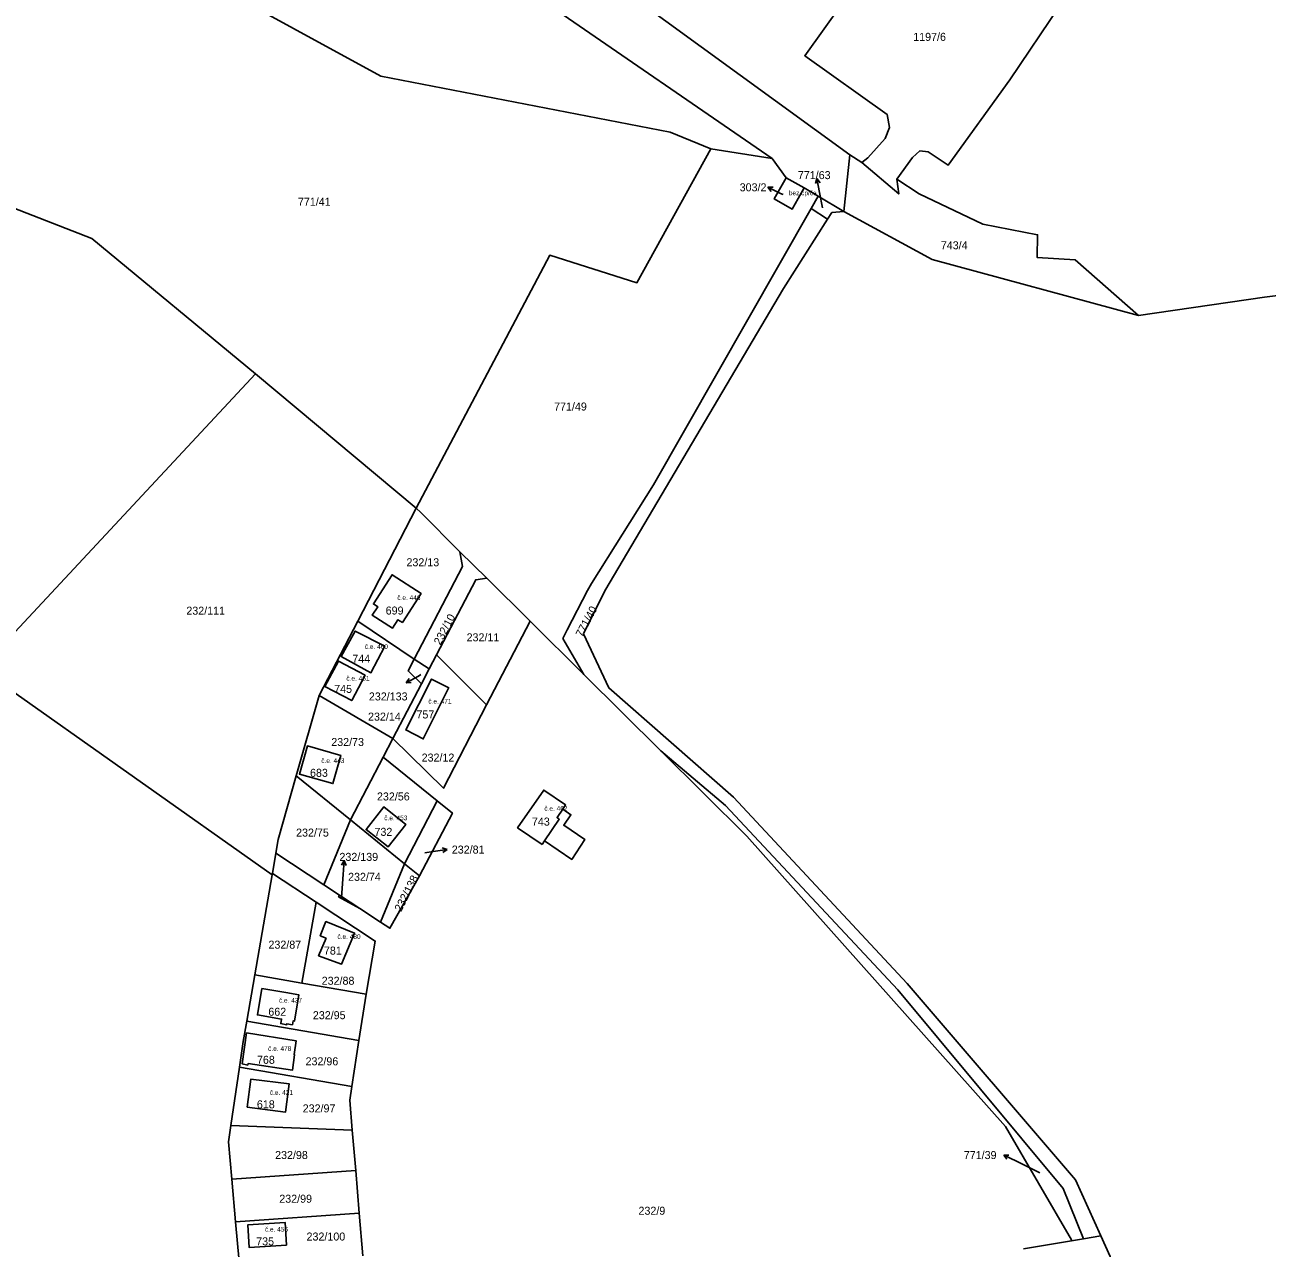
# Model space of a CAD drawing. Extents: x -887272 to -880188, y -1026687 to -1021896.
# Drawn here: x -882048.6 to -881784.7, y -1023602.5 to -1023342.6 of the extents above; entities that cross this region are included whole.
import ezdxf

# ---------------------------------------------------------------- set-up
doc = ezdxf.new("R2010")
doc.units = 0
for name, color, linetype in [('Definiční body', 7, 'Continuous'), ('Hranice parcel', 7, 'Continuous'), ('Parcelní čísla', 7, 'Continuous'), ('Polygon budovy', 7, 'Continuous'), ('Pop  PČ popisy', 7, 'Continuous'), ('Vnitřní kresba', 7, 'Continuous')]:
    doc.layers.add(name, color=color, linetype=linetype)

msp = doc.modelspace()

# ---------------------------------------------------------------- linework, layer by layer
at = {"layer": 'Hranice parcel'}
for p, q in [((-881902.88, -1023368.96), (-881889.86, -1023371.02)), ((-881873.32, -1023370.23), (-881874.58, -1023382.3)), ((-881873.32, -1023370.23), (-881870.82, -1023371.88)), ((-881886.87, -1023375.11), (-881889.86, -1023371.02)), ((-881883.05, -1023377.27), (-881886.87, -1023375.11)), ((-881880.08, -1023379.03), (-881883.05, -1023377.27)), ((-881881.58, -1023381.65), (-881880.08, -1023379.03)), ((-881880.08, -1023379.03), (-881874.58, -1023382.3)), ((-881878.1, -1023383.87), (-881881.58, -1023381.65)), ((-881999.63, -1023416.75), (-882058.02, -1023479.44)), ((-881965.46, -1023445.29), (-881999.63, -1023416.75)), ((-881965.46, -1023445.29), (-881977.86, -1023469.33)), ((-881964.49, -1023446.26), (-881965.46, -1023445.29)), ((-881956.17, -1023454.58), (-881964.49, -1023446.26)), ((-881950.44, -1023460.16), (-881956.17, -1023454.58)), ((-881941.26, -1023469.34), (-881950.44, -1023460.16)), ((-881977.86, -1023469.33), (-881986.1, -1023485.08)), ((-881977.86, -1023469.33), (-881965.87, -1023477.36)), ((-881941.26, -1023469.34), (-881950.54, -1023487.1)), ((-881929.87, -1023480.62), (-881941.26, -1023469.34)), ((-881934.3, -1023472.97), (-881929.87, -1023480.62)), ((-881965.87, -1023477.36), (-881962.71, -1023479.48)), ((-881962.71, -1023479.48), (-881961.18, -1023476.49)), ((-881961.18, -1023476.49), (-881950.54, -1023487.1)), ((-881996.08, -1023523.25), (-882058.02, -1023479.44)), ((-881962.71, -1023479.48), (-881964.33, -1023482.66)), ((-881913.49, -1023496.9), (-881929.87, -1023480.62)), ((-881964.33, -1023482.66), (-881970.4, -1023494.24)), ((-881986.1, -1023485.08), (-881990.93, -1023502.21)), ((-881986.1, -1023485.08), (-881970.4, -1023494.24)), ((-881970.4, -1023494.24), (-881972.46, -1023498.24)), ((-881895.21, -1023515.01), (-881913.49, -1023496.9)), ((-881972.46, -1023498.24), (-881979.39, -1023511.53)), ((-881972.46, -1023498.24), (-881961.04, -1023507.47)), ((-881990.93, -1023502.21), (-881979.39, -1023511.53)), ((-881967.93, -1023520.85), (-881961.04, -1023507.47)), ((-881979.39, -1023511.53), (-881985.07, -1023525.34)), ((-881979.39, -1023511.53), (-881967.93, -1023520.85)), ((-881995.28, -1023518.63), (-881996.02, -1023522.93)), ((-881985.07, -1023525.34), (-881995.28, -1023518.63)), ((-881973.03, -1023533.25), (-881967.93, -1023520.85)), ((-881967.93, -1023520.85), (-881964.73, -1023523.44)), ((-881999.76, -1023544.49), (-881996.08, -1023523.25)), ((-881996.02, -1023522.93), (-881996.08, -1023523.25)), ((-881996.02, -1023522.93), (-881986.75, -1023529.02)), ((-881981.77, -1023527.51), (-881985.07, -1023525.34)), ((-881989.73, -1023546.22), (-881986.75, -1023529.02)), ((-881981.77, -1023527.51), (-881977.45, -1023530.34)), ((-881973.03, -1023533.25), (-881977.45, -1023530.34)), ((-882001.46, -1023554.3), (-881999.76, -1023544.49)), ((-881999.76, -1023544.49), (-881989.73, -1023546.22)), ((-881989.73, -1023546.22), (-881976.11, -1023548.58)), ((-881976.11, -1023548.58), (-881977.63, -1023558.42)), ((-882001.46, -1023554.3), (-881977.63, -1023558.42)), ((-881977.63, -1023558.42), (-881979.14, -1023568.21)), ((-882004.86, -1023576.46), (-882003.02, -1023564.08)), ((-882003.02, -1023564.08), (-881979.14, -1023568.21)), ((-882004.86, -1023576.46), (-881979.04, -1023577.48)), ((-881979.04, -1023577.48), (-881978.32, -1023586.01)), ((-882004.66, -1023587.88), (-881978.32, -1023586.01)), ((-881978.32, -1023586.01), (-881977.56, -1023595.07)), ((-882003.86, -1023596.94), (-882004.66, -1023587.88)), ((-881825.37, -1023588.04), (-881820, -1023599.95)), ((-882003.86, -1023596.94), (-881977.56, -1023595.07)), ((-881977.56, -1023595.07), (-881976.82, -1023604.15)), ((-882003.11, -1023605.34), (-882003.86, -1023596.94)), ((-881820, -1023599.95), (-881823.68, -1023600.55)), ((-881836.44, -1023602.65), (-881826.23, -1023600.97)), ((-881826.23, -1023600.97), (-881826.27, -1023600.76)), ((-881823.68, -1023600.55), (-881826.23, -1023600.97))]:
    msp.add_line(p, q, dxfattribs=at)
for points in [[(-881889.86, -1023371.02), (-881937.66, -1023338.14), (-881972.84, -1023309.16), (-881998.01, -1023280.08)], [(-881964.8, -1023301.5), (-881943.98, -1023318.82), (-881873.32, -1023370.23)], [(-881870.82, -1023371.88), (-881869.52, -1023370.84), (-881865.81, -1023366.79), (-881864.94, -1023364.39), (-881865.44, -1023361.64), (-881882.9, -1023349.18), (-881858.96, -1023315.71), (-881828.68, -1023338.43), (-881839.34, -1023354.28), (-881852.45, -1023372.44), (-881856.71, -1023369.6), (-881858.46, -1023369.39), (-881860, -1023370.8), (-881863.33, -1023375.42)], [(-882044.17, -1023338.98), (-882010.08, -1023333.22), (-881972.96, -1023353.48), (-881911.54, -1023365.44), (-881902.88, -1023368.96)], [(-881965.46, -1023445.29), (-881937.09, -1023391.55), (-881918.59, -1023397.41), (-881902.88, -1023368.96)], [(-882081.8, -1023371.16), (-882063.68, -1023376.58), (-882034.36, -1023388.04), (-881999.63, -1023416.75)], [(-881863.33, -1023375.42), (-881862.95, -1023378.53), (-881870.82, -1023371.88)], [(-881886.87, -1023375.11), (-881889.4, -1023379.59), (-881885.57, -1023381.74), (-881883.05, -1023377.27)], [(-881863.33, -1023375.42), (-881858.6, -1023378.54), (-881845.06, -1023384.94), (-881833.44, -1023387.22), (-881833.52, -1023392.08), (-881825.44, -1023392.52), (-881812.02, -1023404.38)], [(-881878.1, -1023383.87), (-881887.44, -1023398.64), (-881925.36, -1023462.88), (-881929.94, -1023472.01), (-881924.53, -1023483.51), (-881898.05, -1023506.74), (-881861.18, -1023546.34), (-881825.37, -1023588.04)], [(-881881.58, -1023381.65), (-881915.08, -1023440.34), (-881928.2, -1023461.3), (-881929.08, -1023462.8)], [(-881874.58, -1023382.3), (-881877.13, -1023382.48), (-881878.1, -1023383.87)], [(-881874.58, -1023382.3), (-881855.84, -1023392.48), (-881812.02, -1023404.38)], [(-881754.99, -1023396.75), (-881785.26, -1023400.48), (-881812.02, -1023404.38)], [(-881956.17, -1023454.58), (-881955.61, -1023457.68), (-881965.87, -1023477.36)], [(-881968.4, -1023469.6), (-881969.34, -1023469.02), (-881970.53, -1023470.82), (-881974.81, -1023468.07), (-881973.64, -1023466.24), (-881974.57, -1023465.64), (-881970.59, -1023459.46), (-881964.43, -1023463.47), (-881968.4, -1023469.6)], [(-881961.18, -1023476.49), (-881952.8, -1023460.5), (-881950.44, -1023460.16)], [(-881929.08, -1023462.8), (-881933.38, -1023471.19), (-881934.3, -1023472.97)], [(-881975.1, -1023480.27), (-881981.44, -1023476.85), (-881978.46, -1023471.42), (-881972.16, -1023474.66), (-881975.1, -1023480.27)], [(-881984.84, -1023483.2), (-881981.95, -1023477.81), (-881976.31, -1023480.81), (-881979.17, -1023486.19), (-881984.84, -1023483.2)], [(-881964.33, -1023482.66), (-881967.19, -1023479.88), (-881965.87, -1023477.36)], [(-881958.55, -1023483.48), (-881958.59, -1023483.58), (-881961.69, -1023489.79), (-881963.96, -1023494.35), (-881967.69, -1023492.44), (-881962.21, -1023481.64), (-881958.55, -1023483.48)], [(-881950.54, -1023487.1), (-881959.68, -1023504.83), (-881970.4, -1023494.24)], [(-881990.29, -1023501.81), (-881988.59, -1023495.84), (-881981.47, -1023497.86), (-881983.17, -1023503.84), (-881990.29, -1023501.81)], [(-881823.68, -1023600.55), (-881828.03, -1023589.87), (-881863.15, -1023547.67), (-881899.78, -1023508.48), (-881913.49, -1023496.9)], [(-881990.93, -1023502.21), (-881994.77, -1023515.72), (-881995.28, -1023518.63)], [(-881938.71, -1023516.74), (-881943.92, -1023513.21), (-881938.38, -1023505.21), (-881933.74, -1023508.37), (-881934.34, -1023509.27), (-881932.58, -1023510.45), (-881934.1, -1023512.69), (-881929.62, -1023515.71), (-881932.43, -1023519.94), (-881938.21, -1023516.01), (-881938.71, -1023516.74)], [(-881961.04, -1023507.47), (-881957.76, -1023510.11), (-881964.73, -1023523.44)], [(-881967.69, -1023512.49), (-881971.43, -1023517.29), (-881976.11, -1023513.59), (-881972.37, -1023508.8), (-881967.69, -1023512.49)], [(-881826.27, -1023600.76), (-881840.27, -1023576.67), (-881895.21, -1023515.01)], [(-881964.73, -1023523.44), (-881971.06, -1023534.55), (-881973.03, -1023533.25)], [(-881986.75, -1023529.02), (-881974.15, -1023537.3), (-881976.11, -1023548.58)], [(-881977.45, -1023530.34), (-881981.97, -1023527.88), (-881981.77, -1023527.51)], [(-881984.59, -1023536.68), (-881985.85, -1023536.17), (-881984.63, -1023533.14), (-881978.56, -1023535.61), (-881981.36, -1023542.21), (-881986.2, -1023540.42), (-881984.59, -1023536.68)], [(-881994.23, -1023554.83), (-881994.06, -1023553.85), (-881999.19, -1023552.97), (-881998.23, -1023547.38), (-881993.16, -1023548.24), (-881990.39, -1023548.72), (-881991.35, -1023554.31), (-881991.62, -1023554.27), (-881991.76, -1023555.08), (-881992.96, -1023554.88), (-881992.99, -1023555.07), (-881994.23, -1023554.83)], [(-882003.02, -1023564.08), (-882002.21, -1023558.65), (-882001.46, -1023554.3)], [(-882001.49, -1023556.8), (-881991, -1023558.46), (-881991.41, -1023561.42), (-881991.3, -1023561.45), (-881991.74, -1023564.69), (-882001.18, -1023563.32), (-882001.24, -1023563.63), (-882002.41, -1023563.41), (-882001.49, -1023556.8)], [(-882001.35, -1023572.58), (-882000.59, -1023566.61), (-881992.44, -1023567.65), (-881993.21, -1023573.63), (-882001.35, -1023572.58)], [(-881979.14, -1023568.21), (-881979.58, -1023571.07), (-881979.04, -1023577.48)], [(-882004.66, -1023587.88), (-882005.37, -1023579.92), (-882004.86, -1023576.46)], [(-881993.01, -1023601.91), (-882000.94, -1023602.43), (-882001.25, -1023597.61), (-881993.3, -1023597.12), (-881993.01, -1023601.91)], [(-881818.23, -1023617.44), (-881818.12, -1023609.45), (-881818.05, -1023604.28), (-881820, -1023599.95)]]:
    msp.add_lwpolyline(points, dxfattribs=at)
at = {"layer": 'Polygon budovy'}
for points in [[(-881886.87, -1023375.11), (-881889.4, -1023379.59), (-881885.57, -1023381.74), (-881883.05, -1023377.27)], [(-881970.59, -1023459.46), (-881974.57, -1023465.64), (-881973.64, -1023466.24), (-881974.81, -1023468.07), (-881970.53, -1023470.82), (-881969.34, -1023469.02), (-881968.4, -1023469.6), (-881964.43, -1023463.47)], [(-881981.44, -1023476.85), (-881975.1, -1023480.27), (-881972.16, -1023474.66), (-881978.46, -1023471.42)], [(-881984.84, -1023483.2), (-881979.17, -1023486.19), (-881976.31, -1023480.81), (-881981.95, -1023477.81)], [(-881962.21, -1023481.64), (-881967.69, -1023492.44), (-881963.96, -1023494.35), (-881961.69, -1023489.79), (-881958.59, -1023483.58), (-881958.55, -1023483.48)], [(-881988.59, -1023495.84), (-881990.29, -1023501.81), (-881983.17, -1023503.84), (-881981.47, -1023497.86)], [(-881938.71, -1023516.74), (-881938.21, -1023516.01), (-881935.06, -1023511.39), (-881935.55, -1023511.06), (-881934.34, -1023509.27), (-881933.74, -1023508.37), (-881938.38, -1023505.21), (-881943.92, -1023513.21)], [(-881976.11, -1023513.59), (-881971.43, -1023517.29), (-881967.69, -1023512.49), (-881972.37, -1023508.8)], [(-881984.59, -1023536.68), (-881986.2, -1023540.42), (-881981.36, -1023542.21), (-881978.56, -1023535.61), (-881984.63, -1023533.14), (-881985.85, -1023536.17)], [(-881998.23, -1023547.38), (-881999.19, -1023552.97), (-881994.06, -1023553.85), (-881994.23, -1023554.83), (-881992.99, -1023555.07), (-881992.96, -1023554.88), (-881991.76, -1023555.08), (-881991.62, -1023554.27), (-881991.35, -1023554.31), (-881990.39, -1023548.72), (-881993.16, -1023548.24)], [(-882002.41, -1023563.41), (-882001.24, -1023563.63), (-882001.18, -1023563.32), (-881991.74, -1023564.69), (-881991.3, -1023561.45), (-881991.41, -1023561.42), (-881991, -1023558.46), (-882001.49, -1023556.8)], [(-882000.59, -1023566.61), (-882001.35, -1023572.58), (-881993.21, -1023573.63), (-881992.44, -1023567.65)], [(-881993.01, -1023601.91), (-881993.3, -1023597.12), (-882001.25, -1023597.61), (-882000.94, -1023602.43)]]:
    msp.add_lwpolyline(points, close=True, dxfattribs=at)
at = {"layer": 'Pop  PČ popisy'}
for p, q in [((-881880.34, -1023375.27), (-881880.64, -1023376.35)), ((-881879.77, -1023378.22), (-881880.34, -1023375.27)), ((-881880.34, -1023375.27), (-881879.66, -1023376.16)), ((-881890.74, -1023377.11), (-881889.62, -1023377.1)), ((-881888.04, -1023378.43), (-881890.74, -1023377.11)), ((-881890.74, -1023377.11), (-881890.06, -1023378)), ((-881887.5, -1023378.69), (-881888.04, -1023378.43)), ((-881879.14, -1023381.48), (-881879.77, -1023378.22)), ((-881964.99, -1023480.97), (-881967.61, -1023482.43)), ((-881967.61, -1023482.43), (-881966.98, -1023481.5)), ((-881964.49, -1023480.67), (-881964.99, -1023480.97)), ((-881967.61, -1023482.43), (-881966.5, -1023482.38)), ((-881963.61, -1023518.53), (-881961.87, -1023518.28)), ((-881961.87, -1023518.28), (-881958.9, -1023517.86)), ((-881958.9, -1023517.86), (-881959.96, -1023517.51)), ((-881958.9, -1023517.86), (-881959.82, -1023518.5)), ((-881980.77, -1023520.18), (-881981.34, -1023521.14)), ((-881980.98, -1023523.17), (-881980.77, -1023520.18)), ((-881980.77, -1023520.18), (-881980.34, -1023521.21)), ((-881981.32, -1023528.03), (-881980.98, -1023523.17)), ((-881840.65, -1023582.76), (-881839.53, -1023582.75)), ((-881837.95, -1023584.08), (-881840.65, -1023582.76)), ((-881840.65, -1023582.76), (-881839.97, -1023583.65)), ((-881832.97, -1023586.53), (-881837.95, -1023584.08))]:
    msp.add_line(p, q, dxfattribs=at)
at = {"layer": 'Vnitřní kresba'}
for p, q in [((-881935.55, -1023511.06), (-881934.34, -1023509.27)), ((-881938.21, -1023516.01), (-881935.06, -1023511.39)), ((-881935.06, -1023511.39), (-881935.55, -1023511.06))]:
    msp.add_line(p, q, dxfattribs=at)

# ---------------------------------------------------------------- texts
at = {"layer": 'Definiční body'}
for s, p in [('bez čp/če', (-881886.29, -1023378.82)), ('č.e. 446', (-881969.47, -1023464.82)), ('č.e. 460', (-881976.38, -1023475.21)), ('č.e. 461', (-881980.3, -1023481.96)), ('č.e. 471', (-881962.88, -1023486.83)), ('č.e. 443', (-881985.63, -1023499.45)), ('č.e. 453', (-881972.25, -1023511.62)), ('č.e. 462', (-881938.24, -1023509.61)), ('č.e. 480', (-881982.19, -1023536.83)), ('č.e. 437', (-881994.63, -1023550.38)), ('č.e. 478', (-881996.92, -1023560.63)), ('č.e. 421', (-881996.56, -1023569.97)), ('č.e. 456', (-881997.61, -1023599.03))]:
    msp.add_text(s, height=1, dxfattribs=at).set_placement(p)
at = {"layer": 'Parcelní čísla'}
for s, p in [('1197/6', (-881859.87, -1023346.01)), ('771/63', (-881884.38, -1023375.39)), ('303/2', (-881896.74, -1023377.98)), ('771/41', (-881990.59, -1023381.04)), ('743/4', (-881854.01, -1023390.3)), ('771/49', (-881936.17, -1023424.56)), ('232/13', (-881967.53, -1023457.65)), ('232/111', (-882014.3, -1023467.94)), ('699', (-881971.95, -1023467.91)), ('232/11', (-881954.76, -1023473.6)), ('744', (-881979.04, -1023478.15)), ('745', (-881982.89, -1023484.56)), ('232/133', (-881975.52, -1023486.16)), ('232/14', (-881975.7, -1023490.45)), ('757', (-881965.41, -1023489.99)), ('232/73', (-881983.51, -1023495.84)), ('232/12', (-881964.31, -1023499.15)), ('683', (-881988.02, -1023502.39)), ('232/56', (-881973.8, -1023507.41)), ('232/75', (-881990.98, -1023515.09)), ('732', (-881974.33, -1023514.93)), ('743', (-881940.88, -1023512.75)), ('232/139', (-881981.77, -1023520.25)), ('232/81', (-881957.9, -1023518.7)), ('232/74', (-881979.94, -1023524.49)), ('232/87', (-881996.85, -1023538.9)), ('781', (-881985.07, -1023540.16)), ('232/88', (-881985.54, -1023546.57)), ('662', (-881996.88, -1023553.16)), ('232/95', (-881987.42, -1023553.89)), ('768', (-881999.29, -1023563.37)), ('232/96', (-881988.97, -1023563.69)), ('618', (-881999.31, -1023572.83)), ('232/97', (-881989.58, -1023573.69)), ('232/98', (-881995.44, -1023583.6)), ('771/39', (-881849.13, -1023583.61)), ('232/99', (-881994.55, -1023592.89)), ('232/9', (-881918.24, -1023595.44)), ('735', (-881999.46, -1023601.94)), ('232/100', (-881988.76, -1023600.92))]:
    msp.add_text(s, height=1.7, dxfattribs=at).set_placement(p)
for s, rotation, p in [('232/10', 62, (-881960.34, -1023474.51)), ('771/40', 62, (-881930.2, -1023472.84)), ('232/138', 63, (-881968.67, -1023531.18))]:
    msp.add_text(s, height=1.7, rotation=rotation, dxfattribs=at).set_placement(p)

doc.saveas('drawing.dxf')
